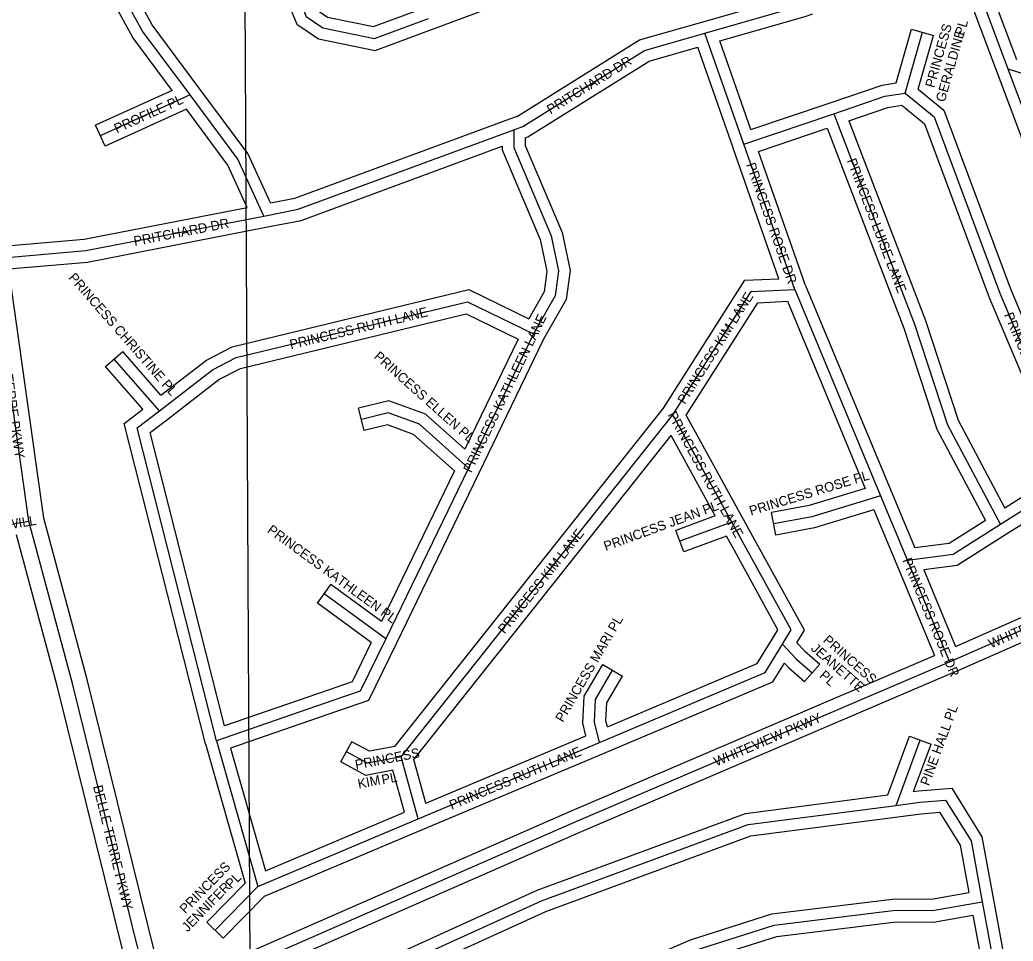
# Model space of a CAD drawing. Extents: x 457167 to 656239, y 1787309 to 1969297.
# Drawn here: x 584541 to 587133, y 1884925 to 1887329 of the extents above; entities that cross this region are included whole.
import ezdxf

# ---------------------------------------------------------------- set-up
doc = ezdxf.new("R2010")
doc.units = 0
for name, color, linetype in [('Level 1', 7, 'Continuous'), ('Level 22', 7, 'Continuous'), ('Level 23', 7, 'Continuous'), ('Level 31', 7, 'Continuous'), ('Level 32', 7, 'Continuous'), ('Level 34', 7, 'Continuous')]:
    doc.layers.add(name, color=color, linetype=linetype)

msp = doc.modelspace()

# ---------------------------------------------------------------- linework, layer by layer
at = {"layer": 'Level 1'}
msp.add_line((585126.331, 1887669.13), (585153.869, 1882363.496), dxfattribs=at)
at = {"layer": 'Level 22'}
msp.add_line((584564.332, 1886020.891), (584467.69, 1886706.173), dxfattribs=at)
msp.add_lwpolyline([(584883.802, 1884765.721), (584678.019, 1885597.759), (584564.332, 1886020.891)], dxfattribs=at)
at = {"layer": 'Level 23'}
msp.add_line((584603.599, 1886028.903), (584511.802, 1886679.831), dxfattribs=at)
for points in [[(584914.364, 1884808.757), (584716.754, 1885607.751), (584603.599, 1886028.901)], [(584836.329, 1884791.061), (584639.284, 1885587.767), (584532.513, 1885985.162)]]:
    msp.add_lwpolyline(points, dxfattribs=at)
at = {"layer": 'Level 31'}
for p, q in [((586998.046, 1887525.731), (587119.574, 1887201.866)), ((586430.631, 1887004.974), (586329.082, 1887294.621)), ((586851.659, 1887138.366), (586896.8, 1887297.192)), ((587119.574, 1887201.866), (587279.082, 1886776.112)), ((587119.574, 1887201.866), (587429.809, 1887104.561)), ((584985.024, 1887133.543), (584750.737, 1887027.083)), ((586430.631, 1887004.974), (586665.819, 1887084.532)), ((586563.822, 1886625.811), (586430.631, 1887004.974)), ((586563.822, 1886625.811), (586787.363, 1886087.571)), ((585881.379, 1886510.008), (585712.148, 1886159.782)), ((584905.204, 1886308.599), (584787.148, 1886444.101)), ((585536.422, 1885405.93), (586245.472, 1886298.408)), ((586399.204, 1886018.844), (586245.472, 1886298.408)), ((585712.148, 1886159.782), (585495.977, 1885714.009)), ((586787.363, 1886087.571), (586857.656, 1885918.346)), ((587224.062, 1886090.756), (587100.51, 1886012.44)), ((584295.168, 1885975.957), (584564.332, 1886020.891)), ((586399.204, 1886018.844), (586263.299, 1885968.918)), ((586432.169, 1885958.782), (586399.204, 1886018.844)), ((586857.656, 1885918.346), (586967.214, 1885654.14)), ((585495.977, 1885714.009), (585335.262, 1885831.407)), ((585357.949, 1885552.816), (585054.318, 1885447.943)), ((585054.318, 1885447.943), (585162.369, 1885067.37)), ((586828.476, 1885279.125), (586891.134, 1885449.191)), ((585580.325, 1885243.663), (586053.98, 1885443.128)), ((585580.325, 1885243.663), (585536.422, 1885405.93)), ((585162.369, 1885067.37), (585580.325, 1885243.663)), ((585162.369, 1885067.37), (585050.51, 1884953.402))]:
    msp.add_line(p, q, dxfattribs=at)
for points in [[(584985.024, 1887133.543), (584860.987, 1887299.964), (584806.158, 1887400.435), (584789.482, 1887494.649), (584791.619, 1887780.101)], [(584791.619, 1887780.101), (584943.614, 1887764.172), (585118.339, 1887660.2), (585236.592, 1887462.153), (585288.197, 1887338.054), (585332.031, 1887308.515), (585466.194, 1887280.986), (585607.824, 1887333.444)], [(586329.082, 1887294.621), (586581.428, 1887366.875), (586599.887, 1887373.749)], [(585830.226, 1887042.837), (585853.46, 1887051.52), (586170.927, 1887249.466), (586329.082, 1887294.621)], [(585177.477, 1886817.535), (585110.015, 1886965.666), (584985.024, 1887133.543)], [(586665.819, 1887084.532), (586798.849, 1887130.101), (586851.659, 1887138.366)], [(586851.659, 1887138.366), (586927.239, 1887076.042), (587099.086, 1886616.082), (587294.467, 1886152.443)], [(586665.819, 1887084.532), (586876.299, 1886535.043), (586962.003, 1886272.7), (587100.51, 1886012.44)], [(585177.477, 1886817.535), (585266.884, 1886835.181), (585830.226, 1887042.837)], [(585830.226, 1887042.837), (585829.819, 1886995.927), (585927.344, 1886765.559), (585947.209, 1886674.249), (585937.864, 1886609.539), (585881.379, 1886510.008)], [(584467.69, 1886706.173), (584713.267, 1886727.153), (585177.477, 1886817.535)], [(586245.472, 1886298.408), (586449.949, 1886620.571), (586563.822, 1886625.811)], [(584905.204, 1886308.599), (585044.083, 1886415.969), (585105.845, 1886447.851), (585709.471, 1886593.608), (585881.379, 1886510.008)], [(585054.318, 1885447.943), (584847.234, 1886264.347), (584905.204, 1886308.599)], [(585712.148, 1886159.782), (585584.187, 1886273.845), (585502.504, 1886303.819), (585432.18, 1886286.498)], [(586787.363, 1886087.571), (586607.876, 1886032.634), (586508.608, 1886014.275)], [(587100.51, 1886012.44), (586976.958, 1885934.124), (586857.656, 1885918.346)], [(586531.555, 1885699.684), (586554.208, 1885737.096), (586432.169, 1885958.782)], [(586967.214, 1885654.14), (587016.872, 1885675.866), (587371.799, 1885832.297)], [(585495.977, 1885714.009), (585429.561, 1885577.408), (585357.949, 1885552.816)], [(586053.98, 1885443.128), (586485.934, 1885625.951), (586531.555, 1885699.684)], [(586531.555, 1885699.684), (586568.059, 1885660.706), (586608.704, 1885624.993)], [(585074.776, 1884835.173), (585988.705, 1885235.615), (586967.214, 1885654.14)], [(586053.98, 1885443.128), (586040.404, 1885496.61), (586043.696, 1885555.513), (586088.051, 1885631.792)], [(585536.422, 1885405.93), (585448.604, 1885389.006), (585393.319, 1885418.931)], [(586828.476, 1885279.125), (586889.879, 1885287.373), (586957.319, 1885293.066), (587023.596, 1885186.396), (587052.88, 1885027.431)], [(585191.986, 1884419.672), (585106.581, 1884667.838), (585902.121, 1885029.96), (586441.934, 1885228.941), (586828.476, 1885279.125)], [(585191.986, 1884419.672), (586302.005, 1884900.475), (586510.145, 1884966.629), (586826.376, 1885005.309), (586922.749, 1885004.765), (587052.88, 1885027.431)], [(587052.88, 1885027.431), (587074.29, 1884909.572), (587103.839, 1884720.789)]]:
    msp.add_lwpolyline(points, dxfattribs=at)
at = {"layer": 'Level 32'}
for p, q in [((585618.312, 1887305.336), (586441.949, 1887612.634)), ((587036.004, 1887509.97), (587142.521, 1887226.111)), ((586981.158, 1887485.345), (587091.487, 1887191.326)), ((586320.824, 1887323.463), (586557.06, 1887391.104)), ((586828.053, 1887165.036), (586867.943, 1887305.394)), ((586867.943, 1887305.394), (586925.658, 1887288.989)), ((586885.881, 1887149.031), (586925.658, 1887288.989)), ((586449.126, 1887042.9), (586367.916, 1887274.534)), ((586402.321, 1886995.048), (586310.128, 1887258.009)), ((587091.482, 1887191.341), (587250.989, 1886765.586)), ((584938.728, 1887145.458), (584738.326, 1887054.396)), ((586449.126, 1887042.9), (586656.205, 1887112.951)), ((584975.41, 1887096.221), (584763.148, 1886999.77)), ((584763.148, 1886999.77), (584738.326, 1887054.396)), ((586468.996, 1886986.281), (586648.119, 1887046.873)), ((586522.149, 1886653.926), (586402.327, 1886995.031)), ((586591.849, 1886636.543), (586468.996, 1886986.28)), ((586591.849, 1886636.543), (586815.069, 1886099.076)), ((586544.186, 1886594.875), (586746.982, 1886106.584)), ((585841.349, 1886496.116), (585702.434, 1886208.631)), ((585907.961, 1886496.062), (585739.16, 1886146.729)), ((584764.529, 1886424.392), (584809.768, 1886463.807)), ((584909.239, 1886349.638), (584809.768, 1886463.807)), ((584861.559, 1886313.024), (584764.529, 1886424.392)), ((585439.355, 1886257.368), (585425.006, 1886315.628)), ((585519.842, 1885433.286), (586220.995, 1886315.826)), ((586425.493, 1886033.3), (586280.311, 1886297.314)), ((585569.34, 1885399.133), (586240.913, 1886244.44)), ((586356.1, 1886034.97), (586240.913, 1886244.44)), ((585675.263, 1886152.472), (585484.661, 1885759.426)), ((585739.142, 1886146.691), (585522.97, 1885700.918)), ((586815.069, 1886099.078), (586876.535, 1885951.104)), ((587208, 1886116.094), (587111.787, 1886055.107)), ((586770.106, 1886050.913), (586829.952, 1885906.838)), ((587240.124, 1886065.416), (587116.573, 1885987.1)), ((586356.1, 1886034.97), (586252.955, 1885997.079)), ((586458.47, 1885973.216), (586425.504, 1886033.279)), ((586514.064, 1885984.774), (586503.151, 1886043.776)), ((586273.645, 1885940.756), (586252.955, 1885997.079)), ((586385.324, 1885981.782), (586273.645, 1885940.756)), ((586405.87, 1885944.346), (586385.324, 1885981.782)), ((586829.944, 1885906.855), (586928.138, 1885670.054)), ((586900.342, 1885893.73), (586983.211, 1885693.885)), ((585317.566, 1885807.181), (585352.959, 1885855.633)), ((585484.661, 1885759.427), (585352.959, 1885855.633)), ((585458.032, 1885704.573), (585317.566, 1885807.181)), ((586062.116, 1885646.873), (586113.986, 1885616.711)), ((586628.506, 1885647.531), (586588.903, 1885602.456)), ((585348.155, 1885581.173), (585075.374, 1885486.955)), ((585367.693, 1885524.442), (585090.926, 1885428.847)), ((585600.319, 1885284.635), (586018.554, 1885460.761)), ((586806.604, 1885306.536), (586862.984, 1885459.562)), ((586862.984, 1885459.562), (586919.285, 1885438.818)), ((585025.344, 1885440.156), (585128.75, 1885075.943)), ((585090.926, 1885428.847), (585181.965, 1885108.195)), ((585379.039, 1885392.546), (585407.598, 1885445.315)), ((586873.847, 1885315.489), (586919.285, 1885438.818)), ((585600.319, 1885284.634), (585569.34, 1885399.133)), ((585591.969, 1885216.013), (586065.624, 1885415.479)), ((585544.524, 1885261.121), (585514.74, 1885371.198)), ((585181.966, 1885108.195), (585544.524, 1885261.121)), ((585179.569, 1885042.062), (585591.984, 1885216.02)), ((585128.749, 1885075.944), (585029.1, 1884974.417)), ((585179.57, 1885042.063), (585071.922, 1884932.387)), ((585071.922, 1884932.387), (585029.1, 1884974.417))]:
    msp.add_line(p, q, dxfattribs=at)
for points in [[(584938.728, 1887145.457), (584835.668, 1887283.733), (584777.472, 1887390.372), (584759.461, 1887492.126), (584761.648, 1887783.856)], [(584828.99, 1887806.349), (584953.293, 1887793.323), (585140.204, 1887682.099), (585263.46, 1887475.673), (585312.437, 1887357.896), (585343.874, 1887336.711), (585463.819, 1887312.099), (585572.602, 1887352.389)], [(585009.079, 1887151.471), (584886.306, 1887316.195), (584834.843, 1887410.496), (584819.502, 1887497.171), (584821.372, 1887746.818)], [(584821.372, 1887746.818), (584933.934, 1887735.021), (585096.473, 1887638.301), (585209.724, 1887448.633), (585263.957, 1887318.211), (585320.188, 1887280.319), (585468.569, 1887249.872), (585618.244, 1887305.311)], [(586367.916, 1887274.533), (586590.806, 1887338.353), (586610.357, 1887345.634)], [(585819.849, 1887070.986), (585840.139, 1887078.57), (586158.634, 1887277.155), (586320.845, 1887323.47)], [(585860.047, 1887021.952), (585866.781, 1887024.47), (586183.22, 1887221.776), (586310.128, 1887258.01)], [(586656.096, 1887112.914), (586791.613, 1887159.335), (586828.053, 1887165.036)], [(585194.946, 1886851.561), (585135.99, 1886981.013), (585009.088, 1887151.46)], [(586885.881, 1887149.031), (586952.529, 1887094.074), (587126.972, 1886627.162), (587319.213, 1886170.976)], [(585134.412, 1886839.713), (585084.04, 1886950.317), (584975.41, 1887096.221)], [(586704.958, 1887066.226), (586806.084, 1887100.868), (586842.978, 1887106.641)], [(586842.978, 1887106.641), (586901.95, 1887058.011), (587071.2, 1886605.003), (587261.054, 1886154.481)], [(585194.946, 1886851.561), (585258.739, 1886864.154), (585819.849, 1887070.986)], [(586704.958, 1887066.226), (586904.583, 1886545.074), (586989.711, 1886284.494), (587111.787, 1886055.106)], [(586648.118, 1887046.873), (586848.014, 1886525.013), (586934.295, 1886260.906), (587060.964, 1886022.891)], [(585860.048, 1887021.953), (585859.873, 1887001.891), (585956.063, 1886774.675), (585977.675, 1886675.327), (585966.747, 1886599.651), (585907.962, 1886496.062)], [(585183.287, 1886788.101), (585275.027, 1886806.209), (585799.85, 1886999.665)], [(585799.851, 1886999.665), (585799.765, 1886989.964), (585898.624, 1886756.444), (585916.741, 1886673.17), (585908.979, 1886619.426), (585869.183, 1886549.298)], [(584506.633, 1886739.61), (584709.111, 1886756.908), (585134.412, 1886839.713)], [(584511.802, 1886679.831), (584717.422, 1886697.399), (585183.211, 1886788.086)], [(586220.994, 1886315.826), (586432.981, 1886649.822), (586522.149, 1886653.925)], [(584909.239, 1886349.639), (585027.894, 1886441.375), (585095.293, 1886476.166), (585712.902, 1886625.3), (585869.184, 1886549.298)], [(586280.311, 1886297.313), (586466.916, 1886591.319), (586544.186, 1886594.875)], [(584923.554, 1886284.865), (585060.27, 1886390.564), (585116.398, 1886419.536), (585706.039, 1886561.916), (585841.348, 1886496.116)], [(585702.434, 1886208.631), (585599.884, 1886300.041), (585504.231, 1886335.141), (585425.006, 1886315.628)], [(585025.343, 1885440.156), (584813.283, 1886276.174), (584861.559, 1886313.024)], [(585075.374, 1885486.955), (584881.184, 1886252.521), (584923.408, 1886284.752)], [(585675.263, 1886152.472), (585568.489, 1886247.648), (585500.777, 1886272.496), (585439.355, 1886257.368)], [(586746.982, 1886106.584), (586600.735, 1886061.823), (586503.151, 1886043.776)], [(586770.105, 1886050.913), (586615.018, 1886003.445), (586514.064, 1885984.774)], [(587060.964, 1886022.891), (586966.475, 1885963), (586876.535, 1885951.104)], [(586568.995, 1885703.594), (586588.847, 1885736.382), (586458.451, 1885973.25)], [(587116.572, 1885987.101), (586987.44, 1885905.249), (586900.342, 1885893.729)], [(586505.894, 1885715.222), (586519.569, 1885737.811), (586405.889, 1885944.314)], [(586983.211, 1885693.885), (587004.809, 1885703.335), (587359.699, 1885859.75)], [(586979.239, 1885626.655), (587028.934, 1885648.396), (587383.899, 1885804.845)], [(586074.463, 1885484.374), (586465.447, 1885649.857), (586505.894, 1885715.222)], [(585458.032, 1885704.573), (585408.03, 1885601.735), (585348.205, 1885581.191)], [(585522.957, 1885700.891), (585451.091, 1885553.081), (585367.693, 1885524.442)], [(586568.996, 1885703.595), (586588.958, 1885682.28), (586628.506, 1885647.531)], [(585063.619, 1884863.036), (585976.786, 1885263.146), (586928.138, 1885670.054)], [(586018.554, 1885460.761), (586010.194, 1885493.689), (586014.144, 1885564.372), (586062.116, 1885646.873)], [(586065.674, 1885415.501), (586506.422, 1885602.045), (586536.448, 1885650.571)], [(586536.448, 1885650.571), (586547.161, 1885639.133), (586588.903, 1885602.456)], [(585085.934, 1884807.307), (586000.624, 1885208.083), (586979.012, 1885626.556)], [(586074.464, 1885484.374), (586070.615, 1885499.531), (586073.249, 1885546.654), (586113.986, 1885616.711)], [(585519.842, 1885433.286), (585453.455, 1885420.494), (585407.598, 1885445.315)], [(585514.74, 1885371.198), (585443.754, 1885357.519), (585379.039, 1885392.546)], [(586873.847, 1885315.489), (586886.618, 1885317.206), (586973.104, 1885324.506), (587052.072, 1885197.411), (587082.384, 1885032.866)], [(585163.619, 1884409.91), (585069.343, 1884683.851), (585890.703, 1885057.724), (586434.724, 1885258.258), (586806.604, 1885306.536)], [(585209.806, 1884460.085), (585143.819, 1884651.826), (585913.539, 1885002.195), (586449.144, 1885199.625), (586832.339, 1885249.374)], [(586832.471, 1885249.391), (586893.14, 1885257.541), (586941.534, 1885261.626), (586995.12, 1885175.381), (587017.889, 1885051.788)], [(585209.806, 1884460.085), (586291.473, 1884928.607), (586503.724, 1884996.068), (586824.632, 1885035.319), (586920.239, 1885034.781), (587017.889, 1885051.788)], [(587082.398, 1885032.793), (587103.874, 1884914.574), (587133.478, 1884725.427)], [(585229.391, 1884403.179), (586312.539, 1884872.343), (586516.566, 1884937.191), (586828.119, 1884975.298), (586925.259, 1884974.749), (587028.688, 1884992.763)], [(587028.687, 1884992.763), (587044.708, 1884904.571), (587068.421, 1884753.067)]]:
    msp.add_lwpolyline(points, dxfattribs=at)

# ---------------------------------------------------------------- texts
at = {"layer": 'Level 34'}
for s, height, rotation, p in [('PRINCESS', 25, 74.1332, (586927.349, 1887150.723)), ('PL', 25, 74.1332, (587005.034, 1887286.519)), ('GERALDINE', 25, 74.1332, (586954.884, 1887113.251)), ('PRITCHARD DR', 25, 31.943458, (585926.199, 1887082.145)), ('PROFILE PL', 25, 24.436125, (584793.909, 1887032.972)), ('PRINCESS ROSE DR', 25, 289.354472, (586436.113, 1886951.658)), ('PRINCESS LUISE LANE', 24.99916, 290.958586, (586699.229, 1886962.371)), ('PRITCHARD DR', 25, 11.017117, (584840.638, 1886739.219)), ('PRINCESS CHRISTINE PL', 25, 311.064083, (584666.439, 1886655.532)), ('PRINCESS KIM LANE', 25, 57.595697, (586276.741, 1886324.353)), ('PRINCESS RUTH LANE', 25, 13.574864, (585248.479, 1886469.435)), ('PRINCESS KATHLEEN LANE', 25, 64.208953, (585719.219, 1886145.693)), ('PRINCESS DELORES LANE', 25, 292.850353, (587109.304, 1886559.649)), ('BELLE TERRE PKWY', 24.99916, 278.026453, (584482.063, 1886514.755)), ('PRINCESS ELLEN PL', 25, 318.286333, (585463.147, 1886447.975)), ('PRINCESS RUTH LANE', 25, 298.806025, (586231.026, 1886298.738)), ('PRINCESS ROSE PL', 25, 17.017544, (586449.162, 1886035.202)), ('PRINCESS JEAN PL', 25, 20.170794, (586070.249, 1885942.686)), ('WHIPPOORWILL', 25, 9.477028, (584325.095, 1885968.281)), ('PRINCESS KATHLEEN PL', 25, 323.852575, (585184.679, 1885993.307)), ('PRINCESS KIM LANE', 25, 51.532964, (585806.102, 1885725.284)), ('PRINCESS ROSE DR', 25, 292.52155, (586843.886, 1885918.926)), ('WHITEVIEW PKWY', 25, 23.784497, (587076.166, 1885688.341)), ('PRINCESS MARI PL', 25, 59.822592, (585958.425, 1885494.261)), ('PRINCESS', 25, 318.6955, (586635.355, 1885707.249)), ('JEANETTE', 25, 318.6955, (586603.801, 1885686.081)), ('PL', 25, 318.6955, (586625.921, 1885615.381)), ('PINE HALL PL', 25, 69.773819, (586913.604, 1885328.556)), ('WHITEVIEW PKWY', 24.99916, 23.156675, (586359.083, 1885380.438)), ('PRINCESS', 25, 10.9074, (585418.28, 1885372.605)), ('PRINCESS RUTH LANE', 25, 22.836303, (585668.304, 1885267.151)), ('KIM', 25, 10.9074, (585425.246, 1885322.826)), ('PL', 25, 10.9074, (585487.494, 1885333.791)), ('BELLE TERRE PKWY', 25, 283.891189, (584731.686, 1885328.71)), ('PRINCESS', 25, 45.5342, (584972.914, 1884995.107)), ('PL', 25, 45.5342, (585092.584, 1885060.162)), ('JENNIFER', 25, 45.5342, (584978.424, 1884947.423))]:
    msp.add_text(s, height=height, rotation=rotation, dxfattribs=at).set_placement(p)

doc.saveas('drawing.dxf')
